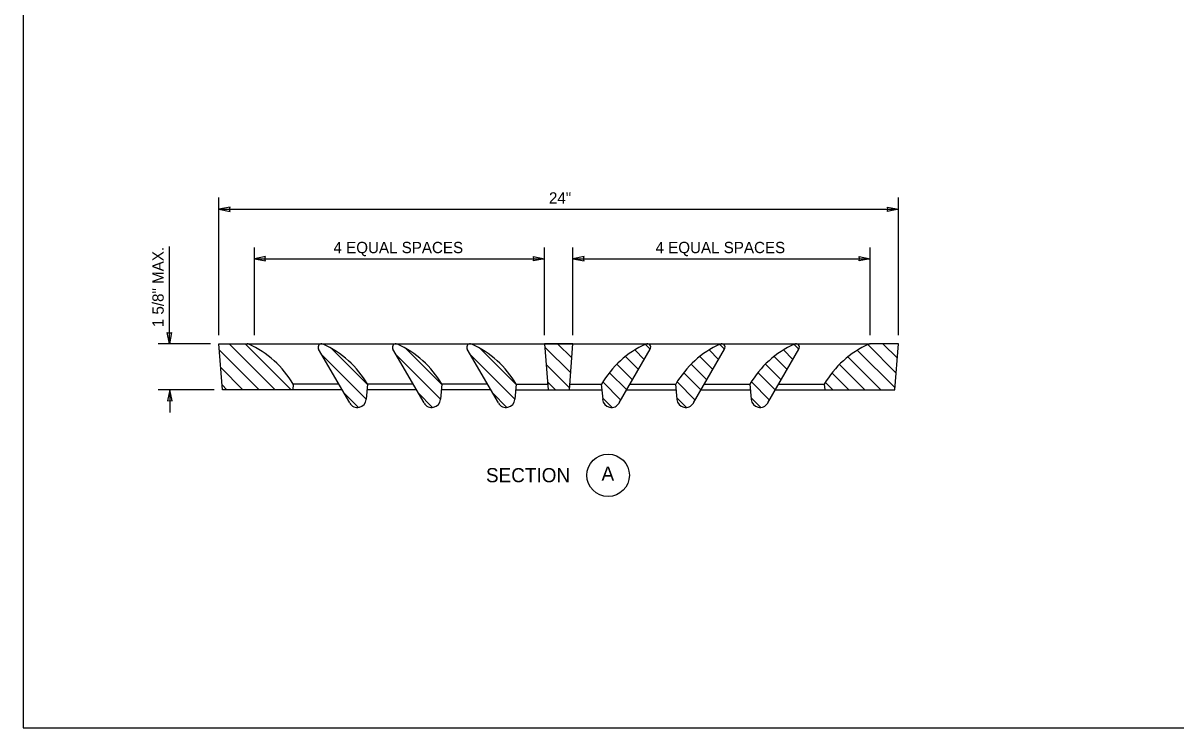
# Model space of a CAD drawing. Extents: x 99862 to 103151, y 100000 to 102076.
# Drawn here: x 99862 to 101491, y 100000 to 100996 of the extents above; entities that cross this region are included whole.
import ezdxf

# ---------------------------------------------------------------- set-up
doc = ezdxf.new("R2010")
doc.units = 0
for name, color, linetype in [('Level 1', 7, 'Continuous'), ('Level 15', 7, 'Continuous'), ('Level 17', 7, 'Continuous'), ('Level 2', 7, 'Continuous'), ('Level 20', 7, 'Continuous'), ('Level 60', 7, 'Continuous'), ('Level 9', 7, 'Continuous')]:
    doc.layers.add(name, color=color, linetype=linetype)

msp = doc.modelspace()

# ---------------------------------------------------------------- linework, layer by layer
at = {"layer": 'Level 1'}
for p, q in [((100178.8, 100542.4), (101058.8, 100542.4)), ((100308.3, 100485.1), (100243.7, 100485.1)), ((100413.3, 100485.1), (100348.7, 100485.1)), ((100518.3, 100485.1), (100453.7, 100485.1)), ((100558.7, 100485.1), (100603.3, 100485.1)), ((100634.4, 100485.1), (100679, 100485.1)), ((100719.4, 100485.1), (100784, 100485.1)), ((100824.4, 100485.1), (100889, 100485.1)), ((100929.4, 100485.1), (100994, 100485.1)), ((100312.7, 100477.4), (100243, 100477.4)), ((100417.7, 100477.4), (100348, 100477.4)), ((100522.7, 100477.4), (100453, 100477.4)), ((100558, 100477.4), (100603.8, 100477.4)), ((100633.8, 100477.4), (100679.7, 100477.4)), ((100715, 100477.4), (100784.7, 100477.4)), ((100820, 100477.4), (100889.7, 100477.4)), ((100925, 100477.4), (100994.7, 100477.4))]:
    msp.add_line(p, q, dxfattribs=at)
msp.add_lwpolyline([(99862, 99999.5), (103151, 99999.5), (103151, 102075.5), (99862, 102075.5)], close=True, dxfattribs=at)
at = {"layer": 'Level 15'}
for p, q in [((100138.8, 100554.4), (100138.8, 100749.1)), ((101098.8, 100554.4), (101098.8, 100749.1)), ((100138.8, 100732.4), (101098.8, 100732.4)), ((100068.8, 100542.4), (100068.8, 100679.9)), ((100188.8, 100554.4), (100188.8, 100678.4)), ((100598.8, 100554.4), (100598.8, 100678.4)), ((100638.8, 100554.4), (100638.8, 100678.4)), ((101058.8, 100554.4), (101058.8, 100678.4)), ((100188.8, 100662.4), (100598.8, 100662.4)), ((100638.8, 100662.4), (101058.8, 100662.4)), ((100126.9, 100542.4), (100052.7, 100542.4)), ((100131.9, 100477.4), (100052.9, 100477.4)), ((100069.4, 100477.4), (100069.4, 100445.4))]:
    msp.add_line(p, q, dxfattribs=at)
for points in [[(100138.8, 100732.4), (100154.6, 100729.4), (100153.8, 100732.4), (100154.6, 100735.5)], [(101098.8, 100732.4), (101083.1, 100729.4), (101083.8, 100732.4), (101083.1, 100735.5)], [(100188.8, 100662.4), (100204.6, 100659.4), (100203.8, 100662.4), (100204.6, 100665.5)], [(100598.8, 100662.4), (100583.1, 100659.4), (100583.8, 100662.4), (100583.1, 100665.5)], [(100638.8, 100662.4), (100654.6, 100659.4), (100653.8, 100662.4), (100654.6, 100665.5)], [(101058.8, 100662.4), (101043.1, 100659.4), (101043.8, 100662.4), (101043.1, 100665.5)], [(100068.8, 100542.4), (100065.8, 100558.2), (100068.8, 100557.4), (100071.9, 100558.2)], [(100069.4, 100477.4), (100066.3, 100461.7), (100069.4, 100462.4), (100072.5, 100461.7)]]:
    msp.add_lwpolyline(points, close=True, dxfattribs=at)
at = {"layer": 'Level 17'}
for p, q in [((100195.4, 100477.4), (100139.6, 100533.3)), ((100218, 100477.4), (100153, 100542.4)), ((100240.6, 100477.4), (100175.6, 100542.4)), ((100348.7, 100484.8), (100297.4, 100536.1)), ((100453.7, 100484.8), (100402.4, 100536.1)), ((100558.7, 100484.8), (100507.4, 100536.1)), ((100635.7, 100501.2), (100599.2, 100537.7)), ((100637.3, 100522.3), (100617.1, 100542.4)), ((100739.7, 100520.2), (100726.2, 100533.7)), ((100748, 100534.6), (100740.9, 100541.6)), ((100844.7, 100520.2), (100831.2, 100533.7)), ((100853, 100534.6), (100845.9, 100541.6)), ((100949.7, 100520.2), (100936.2, 100533.7)), ((100958, 100534.6), (100950.9, 100541.6)), ((101094, 100479.9), (101040.6, 100533.3)), ((101095.6, 100500.9), (101055.3, 100541.3)), ((101097.3, 100521.9), (101076.7, 100542.4)), ((100346.8, 100464), (100284.4, 100526.4)), ((100451.8, 100464), (100389.4, 100526.4)), ((100556.8, 100464), (100494.4, 100526.4)), ((100731.4, 100505.9), (100713, 100524.3)), ((100836.4, 100505.9), (100818, 100524.3)), ((100941.4, 100505.9), (100923, 100524.3)), ((101073.9, 100477.4), (101027.4, 100523.9)), ((100172.7, 100477.4), (100141.4, 100508.7)), ((100634.1, 100480.2), (100601.1, 100513.2)), ((100714.8, 100477.2), (100690.3, 100501.7)), ((100723.1, 100491.5), (100701, 100513.7)), ((100819.8, 100477.2), (100795.3, 100501.7)), ((100828.1, 100491.5), (100806, 100513.7)), ((100924.8, 100477.2), (100900.3, 100501.7)), ((100933.1, 100491.5), (100911, 100513.7)), ((101028.6, 100477.4), (101004.9, 100501.2)), ((101051.2, 100477.4), (101015.5, 100513.2)), ((100150.1, 100477.4), (100143.3, 100484.2)), ((100614.2, 100477.4), (100603, 100488.7)), ((100706.6, 100462.9), (100681, 100488.4)), ((100811.6, 100462.9), (100786, 100488.4)), ((100916.6, 100462.9), (100891, 100488.4)), ((101006, 100477.4), (100995.6, 100487.8)), ((100335.7, 100452.5), (100315.3, 100472.9)), ((100440.7, 100452.5), (100420.3, 100472.9)), ((100545.7, 100452.5), (100525.3, 100472.9)), ((100694.3, 100452.5), (100680.7, 100466.1)), ((100799.3, 100452.5), (100785.7, 100466.1)), ((100904.3, 100452.5), (100890.7, 100466.1))]:
    msp.add_line(p, q, dxfattribs=at)
at = {"layer": 'Level 2'}
for points in [[(100243.7, 100485.1), (100243, 100477.4), (100143.8, 100477.4), (100138.8, 100542.4), (100178.8, 100542.4)], [(100323.5, 100458.7), (100279.5, 100534.9)], [(100428.5, 100458.7), (100384.5, 100534.9)], [(100533.5, 100458.7), (100489.5, 100534.9)], [(100633.8, 100477.4), (100638.8, 100542.4), (100598.8, 100542.4), (100603.8, 100477.4), (100633.8, 100477.4)], [(100704.2, 100458.7), (100748.2, 100534.9)], [(100809.2, 100458.7), (100853.2, 100534.9)], [(100914.2, 100458.7), (100958.2, 100534.9)], [(100994, 100485.1), (100994.7, 100477.4), (101093.8, 100477.4), (101098.8, 100542.4), (101058.8, 100542.4)], [(100348.7, 100485.1), (100346.8, 100463.9)], [(100453.7, 100485.1), (100451.8, 100463.9)], [(100558.7, 100485.1), (100556.8, 100463.9)], [(100679, 100485.1), (100680.9, 100463.9)], [(100784, 100485.1), (100785.9, 100463.9)], [(100889, 100485.1), (100890.9, 100463.9)]]:
    msp.add_lwpolyline(points, dxfattribs=at)
for centre, radius, start, end in [((100178.8, 100537.4), 5, 65.4318, 90), ((100122.7, 100414.7), 140, 30.2285, 65.4318), ((100283.8, 100537.4), 5, 65.4318, 210), ((100227.7, 100414.7), 140, 30.2285, 65.4318), ((100388.8, 100537.4), 5, 65.4318, 210), ((100332.7, 100414.7), 140, 30.2285, 65.4318), ((100493.8, 100537.4), 5, 65.4318, 210), ((100437.7, 100414.7), 140, 30.2285, 65.4318), ((100800, 100414.7), 140, 114.5682, 149.7715), ((100743.8, 100537.4), 5, 330, 114.5682), ((100905, 100414.7), 140, 114.5682, 149.7715), ((100848.8, 100537.4), 5, 330, 114.5682), ((101010, 100414.7), 140, 114.5682, 149.7715), ((100953.8, 100537.4), 5, 330, 114.5682), ((101115, 100414.7), 140, 114.5682, 149.7715), ((101058.8, 100537.4), 5, 90, 114.5682), ((100334.4, 100464.9), 12.5, 210, 355), ((100439.4, 100464.9), 12.5, 210, 355), ((100544.4, 100464.9), 12.5, 210, 355), ((100693.3, 100464.9), 12.5, 185, 330), ((100798.3, 100464.9), 12.5, 185, 330), ((100903.3, 100464.9), 12.5, 185, 330)]:
    msp.add_arc(centre, radius, start, end, dxfattribs=at)
at = {"layer": 'Level 60'}
msp.add_line((99862, 99999.5), (99862, 99999.5), dxfattribs=at)
msp.add_line((99862, 99999.5), (99862, 99999.5), dxfattribs=at)
at = {"layer": 'Level 9'}
msp.add_circle((100688.6, 100356.5), 30, dxfattribs=at)

# ---------------------------------------------------------------- texts
at = {"layer": 'Level 20'}
for s, height, p in [('24"', 16, (100605, 100740.4)), ('4 EQUAL SPACES ', 16, (100300.6, 100670.4)), ('4 EQUAL SPACES ', 16, (100755.6, 100670.4)), ('A', 20, (100679.3, 100348.9)), ('SECTION', 20, (100516, 100346.7))]:
    msp.add_text(s, height=height, dxfattribs=at).set_placement(p)
msp.add_text('1 5/8" MAX.', height=16, rotation=90, dxfattribs=at).set_placement((100060.7, 100565.8))

doc.saveas('drawing.dxf')
